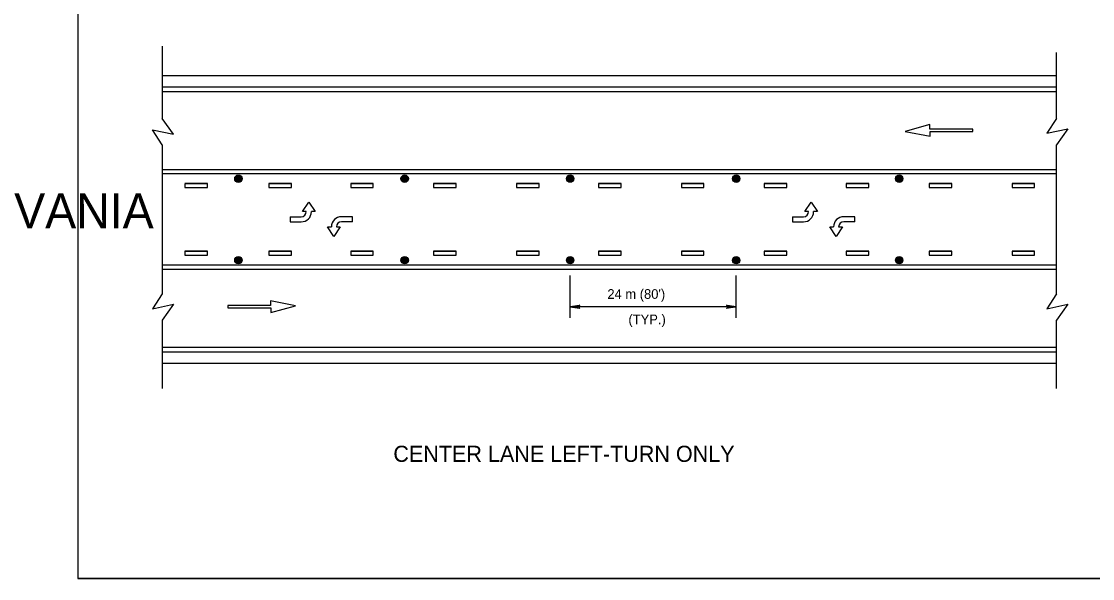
# Model space of a CAD drawing. Extents: x 639362 to 641108, y 298458 to 299646.
# Drawn here: x 640225.9 to 640558.2, y 299066.6 to 299239.5 of the extents above; entities that cross this region are included whole.
import ezdxf

# ---------------------------------------------------------------- set-up
doc = ezdxf.new("R2010")
doc.units = 0
for name, color, linetype in [('1', 7, 'Continuous'), ('2', 7, 'Continuous'), ('3', 7, 'Continuous')]:
    doc.layers.add(name, color=color, linetype=linetype)

# ---------------------------------------------------------------- blocks, each defined once
blk = doc.blocks.new('RARROW')
at = {"layer": '3'}
blk.add_lwpolyline([(-2.2695, 0.285), (-2.184875, 0.12075), (0, 0), (-2.2695, 0.285), (-2.38575, 0.384625), (0, 0), (-2.183125, -0.108), (-2.262875, -0.2705), (0, 0), (-2.38575, -0.379125), (-2.262875, -0.2705)], dxfattribs=at)

msp = doc.modelspace()

# ---------------------------------------------------------------- linework, layer by layer
at = {"layer": '1'}
for p, q in [((640243.31, 299630.63), (640243.31, 299066.63)), ((641029.31, 299066.63), (640243.31, 299066.63)), ((640243.31, 299066.63), (640829.31, 299066.63))]:
    msp.add_line(p, q, dxfattribs=at)
at = {"layer": '2'}
for p, q in [((640269.57, 299231.87), (640269.57, 299209.4)), ((640547.01, 299209.4), (640547.01, 299229.85)), ((640269.57, 299222.76), (640547.01, 299222.76)), ((640269.57, 299219.26), (640547.01, 299219.26)), ((640269.57, 299217.76), (640547.01, 299217.76)), ((640273.06, 299204.51), (640269.57, 299209.4)), ((640547.01, 299209.4), (640543.96, 299204.82)), ((640269.57, 299201.27), (640266.53, 299205.85)), ((640266.53, 299205.85), (640273.06, 299204.51)), ((640507.72, 299207.51), (640500, 299205.4)), ((640507.72, 299206.07), (640507.72, 299207.51)), ((640521.05, 299206.07), (640507.72, 299206.07)), ((640521.05, 299205.37), (640521.05, 299206.07)), ((640543.96, 299204.82), (640550.5, 299206.16)), ((640550.5, 299206.16), (640547.01, 299201.27)), ((640500, 299205.4), (640507.8, 299203.92)), ((640507.8, 299203.92), (640507.8, 299205.37)), ((640507.8, 299205.37), (640521.05, 299205.37)), ((640269.57, 299201.27), (640269.57, 299154.97)), ((640547.01, 299154.97), (640547.01, 299201.27)), ((640547.01, 299193.49), (640269.57, 299193.49)), ((640269.57, 299193.49), (640269.57, 299192.29)), ((640547.01, 299192.29), (640547.01, 299193.49)), ((640269.57, 299192.29), (640547.01, 299192.29)), ((640283.59, 299189.2), (640276.57, 299189.2)), ((640276.57, 299189.2), (640283.59, 299189.18)), ((640283.59, 299187.98), (640283.59, 299189.2)), ((640309.67, 299189.21), (640302.65, 299189.21)), ((640302.65, 299189.21), (640309.67, 299189.19)), ((640309.67, 299187.99), (640309.67, 299189.21)), ((640335.04, 299189.21), (640328.02, 299189.21)), ((640328.02, 299189.21), (640335.04, 299189.19)), ((640335.04, 299187.99), (640335.04, 299189.21)), ((640360.78, 299189.21), (640353.76, 299189.21)), ((640353.76, 299189.21), (640360.78, 299189.19)), ((640360.78, 299187.99), (640360.78, 299189.21)), ((640386.52, 299189.21), (640379.5, 299189.21)), ((640379.5, 299189.21), (640386.52, 299189.19)), ((640386.52, 299187.99), (640386.52, 299189.21)), ((640411.89, 299189.21), (640404.87, 299189.21)), ((640404.87, 299189.21), (640411.89, 299189.19)), ((640411.89, 299187.99), (640411.89, 299189.21)), ((640437.63, 299189.21), (640430.61, 299189.21)), ((640430.61, 299189.21), (640437.63, 299189.19)), ((640437.63, 299187.99), (640437.63, 299189.21)), ((640463.37, 299189.21), (640456.35, 299189.21)), ((640456.35, 299189.21), (640463.37, 299189.19)), ((640463.37, 299187.99), (640463.37, 299189.21)), ((640488.74, 299189.21), (640481.72, 299189.21)), ((640481.72, 299189.21), (640488.74, 299189.19)), ((640488.74, 299187.99), (640488.74, 299189.21)), ((640514.48, 299189.21), (640507.46, 299189.21)), ((640507.46, 299189.21), (640514.48, 299189.19)), ((640514.48, 299187.99), (640514.48, 299189.21)), ((640540.22, 299189.21), (640533.2, 299189.21)), ((640533.2, 299189.21), (640540.22, 299189.19)), ((640540.22, 299187.99), (640540.22, 299189.21)), ((640313.06, 299180.5), (640315.04, 299183.46)), ((640315.04, 299183.46), (640317.02, 299180.5)), ((640468.87, 299180.5), (640470.85, 299183.46)), ((640470.85, 299183.46), (640472.83, 299180.5)), ((640314.25, 299180.5), (640313.06, 299180.5)), ((640317.02, 299180.5), (640315.83, 299180.5)), ((640470.06, 299180.5), (640468.87, 299180.5)), ((640472.83, 299180.5), (640471.64, 299180.5)), ((640309.25, 299178.92), (640309.25, 299177.33)), ((640309.25, 299178.92), (640312.67, 299178.92)), ((640309.25, 299177.33), (640312.67, 299177.33)), ((640322.81, 299172.82), (640320.83, 299175.78)), ((640320.83, 299175.78), (640322.02, 299175.78)), ((640324.79, 299175.78), (640322.81, 299172.82)), ((640323.6, 299175.78), (640324.79, 299175.78)), ((640328.6, 299178.94), (640325.18, 299178.94)), ((640328.6, 299177.36), (640325.18, 299177.36)), ((640328.6, 299177.36), (640328.6, 299178.94)), ((640465.06, 299178.92), (640465.06, 299177.33)), ((640465.06, 299178.92), (640468.48, 299178.92)), ((640465.06, 299177.33), (640468.48, 299177.33)), ((640478.62, 299172.82), (640476.64, 299175.78)), ((640476.64, 299175.78), (640477.83, 299175.78)), ((640480.6, 299175.78), (640478.62, 299172.82)), ((640479.41, 299175.78), (640480.6, 299175.78)), ((640484.41, 299178.94), (640480.99, 299178.94)), ((640484.41, 299177.36), (640480.99, 299177.36)), ((640484.41, 299177.36), (640484.41, 299178.94)), ((640283.59, 299168.21), (640276.57, 299168.21)), ((640276.57, 299168.21), (640283.59, 299168.19)), ((640283.59, 299166.99), (640283.59, 299168.21)), ((640309.67, 299168.21), (640302.65, 299168.21)), ((640302.65, 299168.21), (640309.67, 299168.19)), ((640309.67, 299166.99), (640309.67, 299168.21)), ((640335.04, 299168.21), (640328.02, 299168.21)), ((640328.02, 299168.21), (640335.04, 299168.19)), ((640335.04, 299166.99), (640335.04, 299168.21)), ((640360.78, 299168.21), (640353.76, 299168.21)), ((640353.76, 299168.21), (640360.78, 299168.19)), ((640360.78, 299166.99), (640360.78, 299168.21)), ((640386.52, 299168.21), (640379.5, 299168.21)), ((640379.5, 299168.21), (640386.52, 299168.19)), ((640386.52, 299166.99), (640386.52, 299168.21)), ((640411.89, 299168.21), (640404.87, 299168.21)), ((640404.87, 299168.21), (640411.89, 299168.19)), ((640411.89, 299166.99), (640411.89, 299168.21)), ((640437.63, 299168.21), (640430.61, 299168.21)), ((640430.61, 299168.21), (640437.63, 299168.19)), ((640437.63, 299166.99), (640437.63, 299168.21)), ((640463.37, 299168.21), (640456.35, 299168.21)), ((640456.35, 299168.21), (640463.37, 299168.19)), ((640463.37, 299166.99), (640463.37, 299168.21)), ((640488.74, 299168.21), (640481.72, 299168.21)), ((640481.72, 299168.21), (640488.74, 299168.19)), ((640488.74, 299166.99), (640488.74, 299168.21)), ((640514.48, 299168.21), (640507.46, 299168.21)), ((640507.46, 299168.21), (640514.48, 299168.19)), ((640514.48, 299166.99), (640514.48, 299168.21)), ((640540.22, 299168.21), (640533.2, 299168.21)), ((640533.2, 299168.21), (640540.22, 299168.19)), ((640540.22, 299166.99), (640540.22, 299168.21)), ((640547.01, 299163.89), (640269.57, 299163.89)), ((640269.57, 299163.89), (640269.57, 299162.69)), ((640269.57, 299162.69), (640547.01, 299162.69)), ((640547.01, 299162.69), (640547.01, 299163.89)), ((640396.11, 299147.58), (640396.11, 299160.69)), ((640447.64, 299147.51), (640447.64, 299160.69)), ((640269.57, 299154.97), (640266.53, 299150.39)), ((640310.94, 299151.3), (640303.14, 299152.78)), ((640303.14, 299152.78), (640303.14, 299151.33)), ((640547.01, 299154.97), (640543.96, 299150.39)), ((640266.53, 299150.39), (640273.06, 299151.74)), ((640273.06, 299151.74), (640269.57, 299146.85)), ((640303.14, 299151.33), (640289.89, 299151.33)), ((640289.89, 299151.33), (640289.89, 299150.63)), ((640289.89, 299150.63), (640303.22, 299150.63)), ((640303.22, 299149.18), (640310.94, 299151.3)), ((640303.22, 299150.63), (640303.22, 299149.18)), ((640447.64, 299150.97), (640396.11, 299150.97)), ((640543.96, 299150.39), (640550.5, 299151.74)), ((640550.5, 299151.74), (640547.01, 299146.85)), ((640269.57, 299146.85), (640269.57, 299125.58)), ((640547.01, 299125.58), (640547.01, 299146.85)), ((640269.57, 299138.48), (640547.01, 299138.48)), ((640269.57, 299136.98), (640547.01, 299136.98)), ((640269.57, 299133.48), (640547.01, 299133.48))]:
    msp.add_line(p, q, dxfattribs=at)
for points in [[(640283.59, 299189.18), (640276.57, 299189.18), (640276.57, 299187.98), (640283.59, 299187.98)], [(640309.67, 299189.19), (640302.65, 299189.19), (640302.65, 299187.99), (640309.67, 299187.99)], [(640335.04, 299189.19), (640328.02, 299189.19), (640328.02, 299187.99), (640335.04, 299187.99)], [(640360.78, 299189.19), (640353.76, 299189.19), (640353.76, 299187.99), (640360.78, 299187.99)], [(640386.52, 299189.19), (640379.5, 299189.19), (640379.5, 299187.99), (640386.52, 299187.99)], [(640411.89, 299189.19), (640404.87, 299189.19), (640404.87, 299187.99), (640411.89, 299187.99)], [(640437.63, 299189.19), (640430.61, 299189.19), (640430.61, 299187.99), (640437.63, 299187.99)], [(640463.37, 299189.19), (640456.35, 299189.19), (640456.35, 299187.99), (640463.37, 299187.99)], [(640488.74, 299189.19), (640481.72, 299189.19), (640481.72, 299187.99), (640488.74, 299187.99)], [(640514.48, 299189.19), (640507.46, 299189.19), (640507.46, 299187.99), (640514.48, 299187.99)], [(640540.22, 299189.19), (640533.2, 299189.19), (640533.2, 299187.99), (640540.22, 299187.99)], [(640283.59, 299168.19), (640276.57, 299168.19), (640276.57, 299166.99), (640283.59, 299166.99)], [(640309.67, 299168.19), (640302.65, 299168.19), (640302.65, 299166.99), (640309.67, 299166.99)], [(640335.04, 299168.19), (640328.02, 299168.19), (640328.02, 299166.99), (640335.04, 299166.99)], [(640360.78, 299168.19), (640353.76, 299168.19), (640353.76, 299166.99), (640360.78, 299166.99)], [(640386.52, 299168.19), (640379.5, 299168.19), (640379.5, 299166.99), (640386.52, 299166.99)], [(640411.89, 299168.19), (640404.87, 299168.19), (640404.87, 299166.99), (640411.89, 299166.99)], [(640437.63, 299168.19), (640430.61, 299168.19), (640430.61, 299166.99), (640437.63, 299166.99)], [(640463.37, 299168.19), (640456.35, 299168.19), (640456.35, 299166.99), (640463.37, 299166.99)], [(640488.74, 299168.19), (640481.72, 299168.19), (640481.72, 299166.99), (640488.74, 299166.99)], [(640514.48, 299168.19), (640507.46, 299168.19), (640507.46, 299166.99), (640514.48, 299166.99)], [(640540.22, 299168.19), (640533.2, 299168.19), (640533.2, 299166.99), (640540.22, 299166.99)]]:
    msp.add_lwpolyline(points, dxfattribs=at)
for centre, radius in [((640293.18, 299190.72), 1.15), ((640293.18, 299190.72), 1.07), ((640293.18, 299190.72), 0.985), ((640293.18, 299190.72), 0.904), ((640293.18, 299190.72), 0.822), ((640293.18, 299190.72), 0.741), ((640293.18, 299190.72), 0.659), ((640293.18, 299190.72), 0.578), ((640293.18, 299190.72), 0.496), ((640293.18, 299190.72), 0.414), ((640293.18, 299190.72), 0.333), ((640293.18, 299190.72), 0.251), ((640293.18, 299190.72), 0.17), ((640293.18, 299190.72), 0.0881), ((640344.77, 299190.73), 1.15), ((640344.77, 299190.73), 1.07), ((640344.77, 299190.73), 0.985), ((640344.77, 299190.73), 0.904), ((640344.77, 299190.73), 0.822), ((640344.77, 299190.73), 0.741), ((640344.77, 299190.73), 0.659), ((640344.77, 299190.73), 0.578), ((640344.77, 299190.73), 0.496), ((640344.77, 299190.73), 0.414), ((640344.77, 299190.73), 0.333), ((640344.77, 299190.73), 0.251), ((640344.77, 299190.73), 0.17), ((640344.77, 299190.73), 0.0881), ((640396.11, 299190.75), 1.15), ((640396.11, 299190.75), 1.07), ((640396.11, 299190.75), 0.985), ((640396.11, 299190.75), 0.904), ((640396.11, 299190.75), 0.822), ((640396.11, 299190.75), 0.741), ((640396.11, 299190.75), 0.659), ((640396.11, 299190.75), 0.578), ((640396.11, 299190.75), 0.496), ((640396.11, 299190.75), 0.414), ((640396.11, 299190.75), 0.333), ((640396.11, 299190.75), 0.251), ((640396.11, 299190.75), 0.17), ((640396.11, 299190.75), 0.0881), ((640447.64, 299190.73), 1.15), ((640447.64, 299190.73), 1.07), ((640447.64, 299190.73), 0.985), ((640447.64, 299190.73), 0.904), ((640447.64, 299190.73), 0.822), ((640447.64, 299190.73), 0.741), ((640447.64, 299190.73), 0.659), ((640447.64, 299190.73), 0.578), ((640447.64, 299190.73), 0.496), ((640447.64, 299190.73), 0.414), ((640447.64, 299190.73), 0.333), ((640447.64, 299190.73), 0.251), ((640447.64, 299190.73), 0.17), ((640447.64, 299190.73), 0.0881), ((640498.21, 299190.73), 1.15), ((640498.21, 299190.73), 1.07), ((640498.21, 299190.73), 0.985), ((640498.21, 299190.73), 0.904), ((640498.21, 299190.73), 0.822), ((640498.21, 299190.73), 0.741), ((640498.21, 299190.73), 0.659), ((640498.21, 299190.73), 0.578), ((640498.21, 299190.73), 0.496), ((640498.21, 299190.73), 0.414), ((640498.21, 299190.73), 0.333), ((640498.21, 299190.73), 0.251), ((640498.21, 299190.73), 0.17), ((640498.21, 299190.73), 0.0881), ((640293.18, 299165.43), 1.15), ((640293.18, 299165.43), 1.07), ((640293.18, 299165.43), 0.985), ((640293.18, 299165.43), 0.904), ((640293.18, 299165.43), 0.822), ((640293.18, 299165.43), 0.741), ((640293.18, 299165.43), 0.659), ((640293.18, 299165.43), 0.578), ((640293.18, 299165.43), 0.496), ((640293.18, 299165.43), 0.414), ((640344.76, 299165.45), 1.15), ((640344.76, 299165.45), 1.07), ((640344.76, 299165.45), 0.985), ((640344.76, 299165.45), 0.904), ((640344.76, 299165.45), 0.822), ((640344.76, 299165.45), 0.741), ((640344.76, 299165.45), 0.659), ((640344.76, 299165.45), 0.578), ((640344.76, 299165.45), 0.496), ((640344.76, 299165.45), 0.414), ((640396.11, 299165.44), 1.15), ((640396.11, 299165.44), 1.07), ((640396.11, 299165.44), 0.985), ((640396.11, 299165.44), 0.904), ((640396.11, 299165.44), 0.822), ((640396.11, 299165.44), 0.741), ((640396.11, 299165.44), 0.659), ((640396.11, 299165.44), 0.578), ((640396.11, 299165.44), 0.496), ((640396.11, 299165.44), 0.414), ((640447.63, 299165.42), 1.15), ((640447.63, 299165.42), 1.07), ((640447.63, 299165.42), 0.985), ((640447.63, 299165.42), 0.904), ((640447.63, 299165.42), 0.822), ((640447.63, 299165.42), 0.741), ((640447.63, 299165.42), 0.659), ((640447.63, 299165.42), 0.578), ((640447.63, 299165.42), 0.496), ((640447.63, 299165.42), 0.414), ((640498.21, 299165.44), 1.15), ((640498.21, 299165.44), 1.07), ((640498.21, 299165.44), 0.985), ((640498.21, 299165.44), 0.904), ((640498.21, 299165.44), 0.822), ((640498.21, 299165.44), 0.741), ((640498.21, 299165.44), 0.659), ((640498.21, 299165.44), 0.578), ((640498.21, 299165.44), 0.496), ((640498.21, 299165.44), 0.414), ((640293.18, 299165.43), 0.333), ((640293.18, 299165.43), 0.251), ((640293.18, 299165.43), 0.17), ((640293.18, 299165.43), 0.0881), ((640344.76, 299165.45), 0.333), ((640344.76, 299165.45), 0.251), ((640344.76, 299165.45), 0.17), ((640344.76, 299165.45), 0.0881), ((640396.11, 299165.44), 0.333), ((640396.11, 299165.44), 0.251), ((640396.11, 299165.44), 0.17), ((640396.11, 299165.44), 0.0881), ((640447.63, 299165.42), 0.333), ((640447.63, 299165.42), 0.251), ((640447.63, 299165.42), 0.17), ((640447.63, 299165.42), 0.0881), ((640498.21, 299165.44), 0.333), ((640498.21, 299165.44), 0.251), ((640498.21, 299165.44), 0.17), ((640498.21, 299165.44), 0.0881)]:
    msp.add_circle(centre, radius, dxfattribs=at)
for centre, radius, start, end in [((640312.67, 299180.5), 1.58, 270, 0), ((640312.67, 299180.5), 3.16, 270, 0), ((640468.48, 299180.5), 1.58, 270, 0), ((640468.48, 299180.5), 3.16, 270, 0), ((640325.18, 299175.78), 3.16, 90, 180), ((640325.18, 299175.78), 1.58, 90, 180), ((640480.99, 299175.78), 3.16, 90, 180), ((640480.99, 299175.78), 1.58, 90, 180)]:
    msp.add_arc(centre, radius, start, end, dxfattribs=at)

# ---------------------------------------------------------------- block references
at = {"layer": '2', "xscale": 1.2574347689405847, "yscale": 1.3092961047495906, "rotation": 180}
msp.add_blockref('RARROW', (640396.11, 299150.97), dxfattribs=at)
at = {"layer": '2', "xscale": 1.2574347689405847, "yscale": 1.3092961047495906}
msp.add_blockref('RARROW', (640447.64, 299150.97), dxfattribs=at)

# ---------------------------------------------------------------- texts
at = {"layer": '1'}
msp.add_text('COMMONWEALTH OF PENNSYLVANIA', height=10.7828, dxfattribs=at).set_placement((640000.9, 299175.36))
at = {"layer": '2'}
for s, height, p in [("24 m (80')", 3, (640407.66, 299153.44)), ('(TYP.)', 3, (640414.19, 299145.56)), ('CENTER LANE LEFT-TURN ONLY', 5, (640341.25, 299102.85))]:
    msp.add_text(s, height=height, dxfattribs=at).set_placement(p)

doc.saveas('drawing.dxf')
